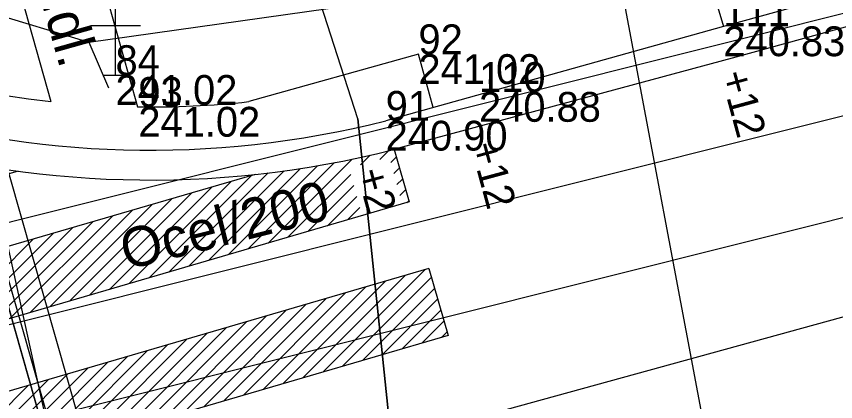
# Model space of a CAD drawing. Extents: x -599432 to -598680, y -1159407 to -1158632.
# Drawn here: x -599014.3 to -599006.05, y -1158880.99 to -1158877.11 of the extents above; entities that cross this region are included whole.
import ezdxf

# ---------------------------------------------------------------- set-up
doc = ezdxf.new("R2010")
doc.units = 0
for name, color, linetype in [('0004 VY - Body podrobné', 7, 'Continuous'), ('0005 VY - Body podrobné - čísla', 7, 'Continuous'), ('0006 VY - Body podrobné - výšky', 7, 'Continuous'), ('0027 ZA - Silnice_cesta zpevněná', 7, 'Continuous'), ('0030 ZA - Chodník', 7, 'Continuous'), ('0031 ZA - Ostatní rozhraní', 7, 'Continuous'), ('0032 TE - Popis povrchu', 7, 'Continuous'), ('0057 ZA - Doprava - BKOM buňky', 7, 'Continuous'), ('0063 ZA - Doprava - vodorovné značení', 7, 'Continuous'), ('0073 TE - Výška obrubníků a zdí', 7, 'Continuous'), ('0202 PV - MUNI', 7, 'Continuous'), ('0203 PV - MUNI - chránička', 7, 'Continuous'), ('0264 PV - TB - parovod mimo provoz', 7, 'Continuous'), ('0301 PV - RWE - popis', 7, 'Continuous'), ('0302 PV - RWE - NTL', 7, 'Continuous'), ('0308 PV - RWE - ochranné pásmo', 7, 'Continuous'), ('0407 PV - TSB - kabelové vedení přibližný zákres', 7, 'Continuous'), ('0454 PV - O2 - kabel zaměřený', 7, 'Continuous'), ('0530 PV - T-mobile - optické kabely', 7, 'Continuous'), ('0652 PV - BKOM - kabely bez rozlišení', 7, 'Continuous'), ('0704 PV - ČD - kabely', 7, 'Continuous')]:
    doc.layers.add(name, color=color, linetype=linetype)

msp = doc.modelspace()

# ---------------------------------------------------------------- linework, layer by layer
at = {"layer": '0004 VY - Body podrobné'}
for p, q in [((-599007.18, -1158877.21), (-599007.18, -1158877.21)), ((-599010.25, -1158877.49), (-599010.25, -1158877.49)), ((-599013.3, -1158877.7), (-599013.3, -1158877.7)), ((-599009.64, -1158877.87), (-599009.64, -1158877.87)), ((-599013.07, -1158878.02), (-599013.07, -1158878.02)), ((-599010.58, -1158878.16), (-599010.58, -1158878.16))]:
    msp.add_line(p, q, dxfattribs=at)
at = {"layer": '0027 ZA - Silnice_cesta zpevněná'}
for p, q in [((-598977.96, -1158869.18), (-599007.18, -1158877.21)), ((-599007.18, -1158877.21), (-599010.58, -1158878.16))]:
    msp.add_line(p, q, dxfattribs=at)
msp.add_arc((-599012.9494, -1158868.8214), 9.6345, 221.45696, 284.23685, dxfattribs=at)
at = {"layer": '0030 ZA - Chodník'}
msp.add_line((-599008.02, -1158874.3), (-599007.18, -1158877.21), dxfattribs=at)
at = {"layer": '0031 ZA - Ostatní rozhraní'}
for p, q in [((-598977.8719, -1158869.5005), (-599007.0919, -1158877.5305)), ((-599015.2666, -1158873.284), (-599013.951, -1158877.9661)), ((-599013.7453, -1158875.6467), (-599013.0785, -1158878.0199)), ((-599010.25, -1158877.49), (-599011.9579, -1158877.9672)), ((-599010.1002, -1158878.026), (-599010.25, -1158877.49)), ((-599007.0919, -1158877.5305), (-599010.5027, -1158878.4499))]:
    msp.add_line(p, q, dxfattribs=at)
for radius, start, end in [(9.1994, 218.84677, 263.74942), (9.9345, 221.46846, 284.25776), (9.1994, 269.19623, 276.18762)]:
    msp.add_arc((-599012.9494, -1158868.8214), radius, start, end, dxfattribs=at)
at = {"layer": '0057 ZA - Doprava - BKOM buňky'}
for p, q in [((-599013.3, -1158877.7), (-599013.3, -1158876.7)), ((-599013.55, -1158877.2), (-599013.05, -1158877.2)), ((-599013.425, -1158877.7), (-599013.175, -1158877.7))]:
    msp.add_line(p, q, dxfattribs=at)
at = {"layer": '0063 ZA - Doprava - vodorovné značení'}
for p, q in [((-599010.6398, -1158878.5498), (-599010.5517, -1158878.4616)), ((-599010.496, -1158878.4481), (-599010.342, -1158878.976)), ((-599011.7637, -1158879.3907), (-599010.9179, -1158878.5449)), ((-599010.834, -1158878.6025), (-599010.7375, -1158878.506)), ((-599010.5282, -1158878.5795), (-599010.4791, -1158878.5305)), ((-599012.3627, -1158879.5655), (-599011.4362, -1158878.639)), ((-599012.163, -1158879.5072), (-599011.2676, -1158878.6118)), ((-599011.9633, -1158879.449), (-599011.0951, -1158878.5808)), ((-599010.498, -1158878.6908), (-599010.4471, -1158878.6399)), ((-599014.2799, -1158878.6664), (-599015.6606, -1158879.0692)), ((-599011.8945, -1158878.6997), (-599015.4646, -1158879.7412)), ((-599012.9617, -1158879.7402), (-599011.9322, -1158878.7107)), ((-599012.762, -1158879.682), (-599011.764, -1158878.6839)), ((-599012.5623, -1158879.6237), (-599011.6027, -1158878.6641)), ((-599011.564, -1158879.3325), (-599010.9309, -1158878.6994)), ((-599013.1613, -1158879.7984), (-599012.1318, -1158878.769)), ((-599011.3643, -1158879.2742), (-599010.9007, -1158878.8106)), ((-599010.4678, -1158878.802), (-599010.4151, -1158878.7493)), ((-599013.5607, -1158879.9149), (-599012.5312, -1158878.8854)), ((-599013.361, -1158879.8567), (-599012.3315, -1158878.8272)), ((-599010.4376, -1158878.9132), (-599010.3831, -1158878.8587)), ((-599010.342, -1158878.976), (-599015.2686, -1158880.4132)), ((-599013.7603, -1158879.9732), (-599012.7308, -1158878.9437)), ((-599011.1647, -1158879.216), (-599010.8705, -1158878.9218)), ((-599010.366, -1158878.983), (-599010.3511, -1158878.9681)), ((-599014.1597, -1158880.0897), (-599013.1302, -1158879.0602)), ((-599013.96, -1158880.0314), (-599012.9305, -1158879.0019)), ((-599010.965, -1158879.1578), (-599010.8403, -1158879.033)), ((-599014.3593, -1158880.1479), (-599013.3298, -1158879.1184)), ((-599014.559, -1158880.2062), (-599013.5295, -1158879.1767)), ((-599014.9583, -1158880.3227), (-599013.9288, -1158879.2932)), ((-599014.7586, -1158880.2644), (-599013.7292, -1158879.2349)), ((-599015.158, -1158880.3809), (-599014.1285, -1158879.3514)), ((-599010.1459, -1158879.648), (-599015.0725, -1158881.0851)), ((-599011.4139, -1158880.7471), (-599010.3845, -1158879.7176)), ((-599011.2143, -1158880.6888), (-599010.1848, -1158879.6593)), ((-599010.1459, -1158879.648), (-599009.9499, -1158880.32)), ((-599011.6136, -1158880.8053), (-599010.5841, -1158879.7758)), ((-599011.0146, -1158880.6306), (-599010.1249, -1158879.7409)), ((-599011.8133, -1158880.8636), (-599010.7838, -1158879.8341)), ((-599010.8149, -1158880.5723), (-599010.0929, -1158879.8503)), ((-599012.2126, -1158880.98), (-599011.1831, -1158879.9506)), ((-599012.0129, -1158880.9218), (-599010.9835, -1158879.8923)), ((-599010.6153, -1158880.5141), (-599010.0609, -1158879.9597)), ((-599012.4123, -1158881.0383), (-599011.3828, -1158880.0088)), ((-599012.8116, -1158881.1548), (-599011.7821, -1158880.1253)), ((-599012.6119, -1158881.0965), (-599011.5825, -1158880.067)), ((-599010.4156, -1158880.4558), (-599010.0289, -1158880.0691)), ((-599013.0113, -1158881.213), (-599011.9818, -1158880.1835)), ((-599010.2159, -1158880.3976), (-599009.9969, -1158880.1785)), ((-599013.2109, -1158881.2713), (-599012.1815, -1158880.2418)), ((-599010.0163, -1158880.3394), (-599009.9649, -1158880.2879)), ((-599009.9499, -1158880.32), (-599014.8765, -1158881.7571)), ((-599013.6103, -1158881.3878), (-599012.5808, -1158880.3583)), ((-599013.4106, -1158881.3295), (-599012.3811, -1158880.3)), ((-599013.8099, -1158881.446), (-599012.7805, -1158880.4165)), ((-599014.2093, -1158881.5625), (-599013.1798, -1158880.533)), ((-599014.0096, -1158881.5043), (-599012.9801, -1158880.4748)), ((-599014.4089, -1158881.6207), (-599013.3795, -1158880.5913)), ((-599014.8083, -1158881.7372), (-599013.7788, -1158880.7077)), ((-599014.6086, -1158881.679), (-599013.5791, -1158880.6495)), ((-599014.8975, -1158881.6851), (-599013.9785, -1158880.766)), ((-599014.9295, -1158881.5756), (-599014.1781, -1158880.8242))]:
    msp.add_line(p, q, dxfattribs=at)
at = {"layer": '0202 PV - MUNI'}
msp.add_lwpolyline([(-599014.9422, -1158877.8009), (-599011.9644, -1158888.2151), (-599011.244, -1158889.3037), (-599007.7539, -1158892.9859), (-599006.5051, -1158893.4182)], dxfattribs=at)
at = {"layer": '0203 PV - MUNI - chránička'}
msp.add_line((-599014.6537, -1158877.7184), (-599011.6759, -1158888.1326), dxfattribs=at)
at = {"layer": '0264 PV - TB - parovod mimo provoz'}
msp.add_line((-598964.2063, -1158868.6584), (-599015.807, -1158882.836), dxfattribs=at)
at = {"layer": '0302 PV - RWE - NTL'}
msp.add_lwpolyline([(-599031.044, -1158884.383), (-598999.16, -1158876.4), (-598995.29, -1158875.42), (-598995.15, -1158875.39), (-598995.04, -1158875.36)], dxfattribs=at)
at = {"layer": '0308 PV - RWE - ochranné pásmo'}
msp.add_lwpolyline([(-599031.689, -1158883.514), (-599031.287, -1158883.413), (-598999.404, -1158875.43), (-598995.518, -1158874.446), (-598995.387, -1158874.418), (-598995.303, -1158874.395), (-598994.903, -1158874.286), (-598994.184, -1158874.697), (-598994.075, -1158875.097), (-598993.966, -1158875.497), (-598994.377, -1158876.216), (-598994.777, -1158876.325), (-598994.913, -1158876.362), (-598995.062, -1158876.394), (-598998.916, -1158877.37), (-599030.801, -1158885.353), (-599031.203, -1158885.454), (-599031.913, -1158885.028), (-599032.014, -1158884.626), (-599032.115, -1158884.224)], close=True, dxfattribs=at)
at = {"layer": '0407 PV - TSB - kabelové vedení přibližný zákres'}
msp.add_line((-599006.2197, -1158887.349), (-599008.2228, -1158876.7211), dxfattribs=at)
at = {"layer": '0454 PV - O2 - kabel zaměřený'}
for points in [[(-599065.99, -1158901.17), (-599063.3, -1158900.18), (-599061.65, -1158898.45), (-599061.04, -1158896.51), (-599061.91, -1158890.95), (-599061.26, -1158889.87), (-599056.07, -1158887.58), (-599053.91, -1158887.47), (-599052.4, -1158886.85), (-599049.09, -1158885.94), (-599048.46, -1158885.4), (-599047.47, -1158884.55), (-599040.18, -1158881.35), (-599032.72, -1158878.67), (-599020.59, -1158875.17), (-599018.58, -1158874.88), (-599016.36, -1158876.44), (-599015.76, -1158876.86), (-599014.99, -1158877.89), (-599012.08, -1158888.14), (-599011.3, -1158889.38), (-599007.9, -1158892.89), (-599006.6, -1158893.35), (-598996.83, -1158890.81)], [(-599009.82, -1158888.17), (-599010.23, -1158884.21), (-599010.86, -1158878.14), (-599011.61, -1158875.82)], [(-599014.99, -1158877.89), (-599012.08, -1158888.14)], [(-599010.86, -1158878.14), (-599010.23, -1158884.21)]]:
    msp.add_lwpolyline(points, dxfattribs=at)
at = {"layer": '0530 PV - T-mobile - optické kabely'}
msp.add_lwpolyline([(-599012.076, -1158888.135), (-599014.988, -1158877.884)], dxfattribs=at)
at = {"layer": '0652 PV - BKOM - kabely bez rozlišení'}
msp.add_line((-599013.57, -1158877.37), (-599013.37, -1158877.83), dxfattribs=at)
for points in [[(-599012.374, -1158857.616), (-599013.19, -1158857.86), (-599018.08, -1158859.1), (-599018.5, -1158859.81), (-599016.73, -1158866.41), (-599019.7, -1158871.25), (-599019.95, -1158872.38), (-599019.48, -1158873.04), (-599018.91, -1158874.17), (-599016.73, -1158875.93), (-599015.62, -1158876.75), (-599013.57, -1158877.37), (-599011.16, -1158877.03), (-599007.55, -1158875.71), (-599007.594, -1158874.617)], [(-599069.54, -1158906.27), (-599056.01, -1158902.46), (-599042.94, -1158898.82), (-599036.88, -1158897.21), (-599035.9, -1158896.65), (-599035.19, -1158895.15), (-599033.43, -1158892.94), (-599032.55, -1158892.85), (-599032.38, -1158891.47), (-599031.43, -1158887.7), (-599033.39, -1158880.98), (-599034.34, -1158877.53), (-599034.11, -1158876.42), (-599020.38, -1158872.59), (-599019.95, -1158872.38), (-599019.48, -1158873.04), (-599018.91, -1158874.17), (-599016.73, -1158875.93), (-599015.62, -1158876.75), (-599013.57, -1158877.37), (-599011.16, -1158877.03), (-599007.55, -1158875.71), (-599006.793, -1158874.464)]]:
    msp.add_lwpolyline(points, dxfattribs=at)
at = {"layer": '0704 PV - ČD - kabely'}
msp.add_lwpolyline([(-598961.1998, -1158881.213), (-599006.8409, -1158893.8814), (-599007.9998, -1158893.3892), (-599012.4449, -1158888.2457), (-599014.7944, -1158877.5617), (-599015.5723, -1158876.5616), (-599018.4457, -1158874.6248), (-599020.4301, -1158874.8947), (-599032.7968, -1158878.3872), (-599047.1639, -1158884.134), (-599048.6403, -1158885.0865), (-599049.561, -1158885.3882), (-599050.6564, -1158886.3724), (-599052.3709, -1158886.6423), (-599054.1807, -1158887.3884), (-599056.3556, -1158887.4043), (-599061.2213, -1158889.6983), (-599062.0071, -1158890.8333), (-599061.1578, -1158896.5405), (-599061.8246, -1158898.4296), (-599063.5073, -1158900.1441), (-599114.0221, -1158914.7334)], dxfattribs=at)

# ---------------------------------------------------------------- texts
at = {"layer": '0005 VY - Body podrobné - čísla'}
for s, p in [('111', (-599007.18, -1158877.21)), ('92', (-599010.25, -1158877.49)), ('84', (-599013.3, -1158877.7)), ('110', (-599009.64, -1158877.87)), ('93', (-599013.07, -1158878.02)), ('91', (-599010.58, -1158878.16))]:
    msp.add_text(s, height=0.3, dxfattribs=at).set_placement(p)
at = {"layer": '0006 VY - Body podrobné - výšky'}
for s, p in [('240.83', (-599007.18, -1158877.51)), ('241.02', (-599010.25, -1158877.79)), ('241.02', (-599013.3, -1158878)), ('240.88', (-599009.64, -1158878.17)), ('241.02', (-599013.07, -1158878.32)), ('240.90', (-599010.58, -1158878.46))]:
    msp.add_text(s, height=0.3, dxfattribs=at).set_placement(p)
at = {"layer": '0032 TE - Popis povrchu'}
msp.add_text('slep.dl.', height=0.4, rotation=285.69492, dxfattribs=at).set_placement((-599014.3132, -1158876.0166))
at = {"layer": '0073 TE - Výška obrubníků a zdí'}
for s, p in [('+12', (-599007.2122, -1158877.6936)), ('+12', (-599009.7299, -1158878.4117)), ('+2', (-599010.8751, -1158878.6758))]:
    msp.add_text(s, height=0.3, rotation=285.18958, dxfattribs=at).set_placement(p)
at = {"layer": '0301 PV - RWE - popis'}
msp.add_text('Ocel/200', height=0.4, rotation=14.05654, dxfattribs=at).set_placement((-599013.1924, -1158879.6633))

doc.saveas('drawing.dxf')
